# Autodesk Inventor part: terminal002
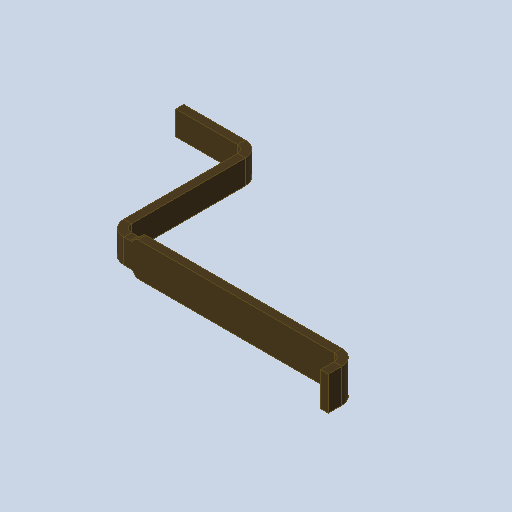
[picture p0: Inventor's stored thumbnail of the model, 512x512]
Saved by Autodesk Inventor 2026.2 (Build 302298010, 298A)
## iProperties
Created: 2026-10
Part Number: terminal002
Material: Générique
Document SubType Name: Modeling
Designer: mel
Density: 1 g/cm^3
Appearance: Par défaut
Author: mel
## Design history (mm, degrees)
feature "Base1"
node "Solide1"
